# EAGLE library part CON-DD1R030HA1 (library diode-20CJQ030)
JAE's DD1R030HA1 30 pole IO-connector
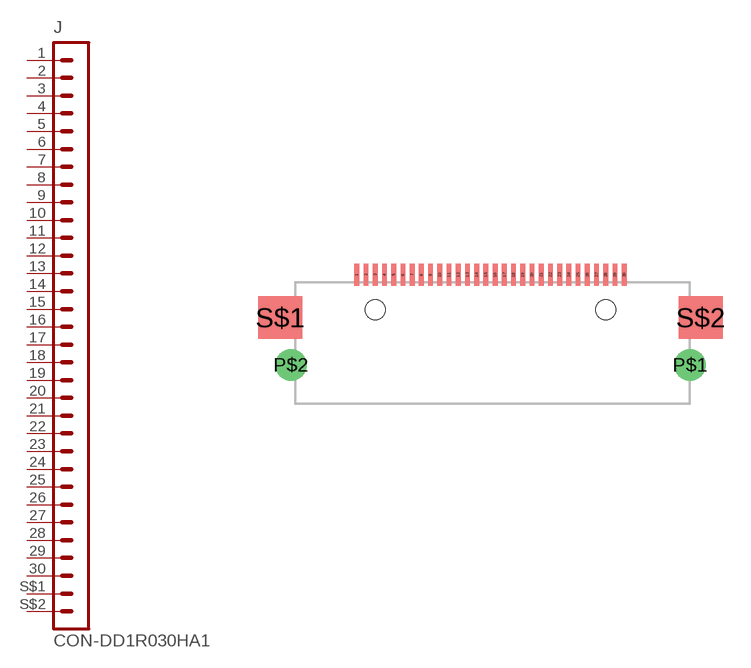
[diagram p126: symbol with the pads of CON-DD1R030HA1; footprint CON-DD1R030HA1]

Designator prefix J

## CON-DD1R030HA1  [CON-DD1R030HA1]
1  1  pas
2  2  pas
3  3  pas
4  4  pas
5  5  pas
6  6  pas
7  7  pas
8  8  pas
9  9  pas
10  10  pas
11  11  pas
12  12  pas
13  13  pas
14  14  pas
15  15  pas
16  16  pas
17  17  pas
18  18  pas
19  19  pas
20  20  pas
21  21  pas
22  22  pas
23  23  pas
24  24  pas
25  25  pas
26  26  pas
27  27  pas
28  28  pas
29  29  pas
30  30  pas
S$1  31  pas
S$2  32  pas

## Footprint CON-DD1R030HA1 (pad centres in mm)
JAE's DD1R030HA1 30 pole IO-connector
smd 0.26 x 1.2: 1 -7.25,1.9; 2 -6.75,1.9; 3 -6.25,1.9; 4 -5.75,1.9; 5 -5.25,1.9; 6 -4.75,1.9; 7 -4.25,1.9; 8 -3.75,1.9; 9 -3.25,1.9; 10 -2.75,1.9; 11 -2.25,1.9; 12 -1.75,1.9; 13 -1.25,1.9; 14 -0.75,1.9; 15 -0.25,1.9; 16 0.25,1.9; 17 0.75,1.9; 18 1.25,1.9; 19 1.75,1.9; 20 2.25,1.9; 21 2.75,1.9; 22 3.25,1.9; 23 3.75,1.9; 24 4.25,1.9; 25 4.75,1.9; 26 5.25,1.9; 27 5.75,1.9; 28 6.25,1.9; 29 6.75,1.9; 30 7.25,1.9
drill 1.1 pad 1.7 round: P$1 10.825,-3; P$2 -10.825,-3
smd 2.4 x 2.3: S$1 -11.4,-0.425; S$2 11.4,-0.425
hole 1.1 at 6.25,0
hole 1.1 at -6.25,0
